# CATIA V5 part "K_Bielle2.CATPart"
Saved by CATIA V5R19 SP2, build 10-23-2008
Part number: Bielle2
Bounding box of the stored display mesh (mm): x 0 to 1, y -1 to 1, z -1 to 17
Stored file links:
  G:\Khaled_CFAO_2011\ST2M\ST2M_GR1\bgaltie\bgaltie\Khaled\CAD_thinkMOTION\K_Bielle2.CATPart
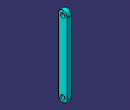
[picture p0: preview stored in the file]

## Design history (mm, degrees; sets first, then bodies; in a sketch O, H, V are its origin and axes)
AxisSystem1: origin (0, 0, 0), X (1, 0, 0), Y (0, 1, 0), Z (0, 0, 1)
Body1 (main body)
  Sketch1 on YZ plane of AxisSystem1, origin (0, 0, 0), H (0, 1, 0), V (0, 0, 1)
    construction line L1 (0, 0) -> (0, 16)
    point P1 (0, 0)
    point P2 (0, 16)
    line L2 (-1, 0) -> (-1, 16)
    line L3 (1, 16) -> (1, 0)
    arc A1 centre (0, 16) radius 1 from (-1, 16) to (1, 16) cw
    arc A2 centre (0, 0) radius 1 from (1, 0) to (-1, 0) cw
    circle A3 centre (0, 16) radius 0.5
    point P7 (0, 16)
    point P8 (0, 0)
    circle A4 centre (0, 0) radius 0.5
    distance L1 L2 = 1
    length L1 = 16
    radius A3 = 0.5
    radius A4 = 0.5
    vertical: L1 V
    tangency: A1 L2, A2 L2, A1 L3, A2 L3
    coincidence: P1 O, P8 O, P7 P2
  Pad1: profile Sketch1, direction (1, 0, 0), length 1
